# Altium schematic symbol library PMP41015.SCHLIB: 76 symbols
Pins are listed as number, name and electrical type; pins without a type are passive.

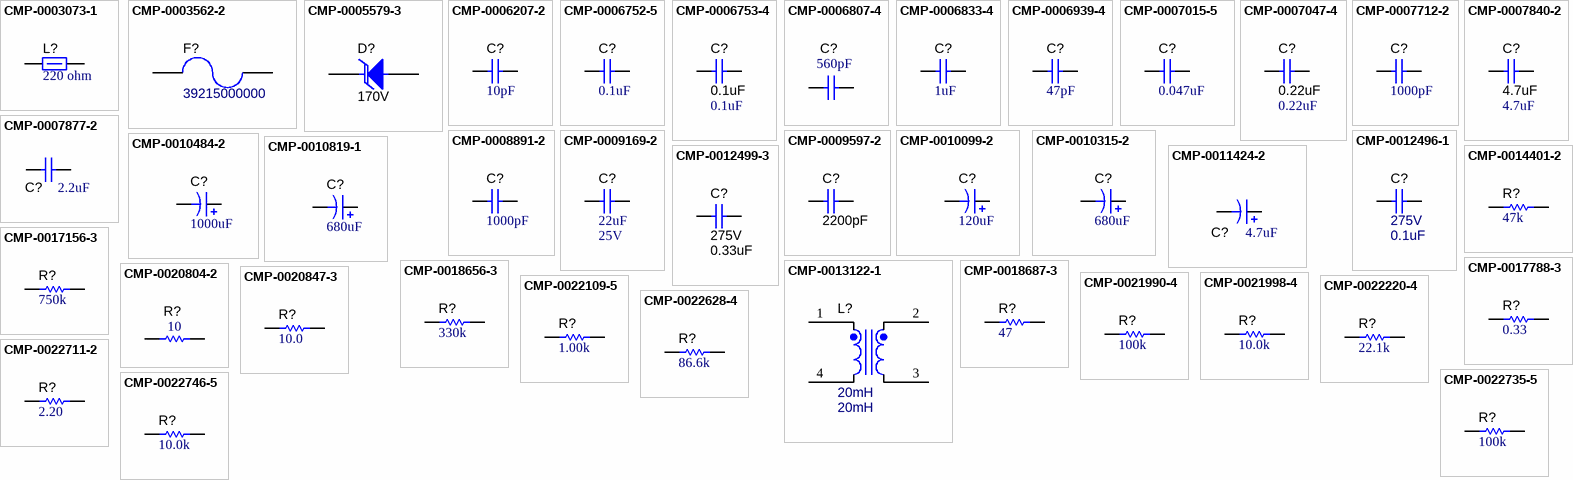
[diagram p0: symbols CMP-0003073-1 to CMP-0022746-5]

## CMP-0003073-1
designator L?  ValueDisplayed: 220 ohm  (hidden comment: CMP-0003073-1)
Ferrite Bead, 220 ohm @ 100 MHz, 2 A, 0805; PartNumber: 742792022; Manufacturer: Wurth Elektronik; Value: 220 ohm; Imax_A: 2A; DCR_ohm: 50m; Value1: 0.05 ohm; SizeAreaWB_mm2: 6.75; SizeArea_mm2: 2.5; SizeX_mm: 2; SizeY_mm: 1.25; SizeZ_mm: 1.45; ZTyp@100MHz_Ohm: 220; Ztyp@1GHz_Ohm: 190.289
footprint 0805_HV (0805 with 30mil clearance between pads)
footprint 0805M (0805 from SM-752 data)
footprint 0805 (0805 from SM-752 data)
footprint 0805L (0805 from SM-752 data)
footprint 0805_HV1 (Custom footprint based on analyzing multiple manufacturer recommendations)
pins: 1, 2

## CMP-0003562-2
designator F?, comment 39215000000
Fuse, 5 A, 250VAC/VDC, TH; Manufacturer: Littelfuse; Irating_A: 5A; VAC_V: 250V
footprint FUSE_392 (LITTELFUSE)
pins: 1, 2

## CMP-0005579-3
designator D?  value 170V  (hidden comment: CMP-0005579-3)
Diode, TVS, Uni, 170 V, 275 Vc, SMB; PartNumber: SMBJ170A-13-F; Manufacturer: Diodes Inc.; Value1: 600W; SizeAreaWB_mm2: 44.156; SizeArea_mm2: 21.336; SizeX_mm: 5.6; SizeY_mm: 3.81; SizeZ_mm: 2.6; AEC Category: Q101; Vbr_Min: 189V; Vc: 275V; Ipp: 2.2A; Vbr_Max: 217.5V
footprint SMB (Molded Diode, 2-Leads, Body 5.4x3.6mm, IPC Medium Density, based on OnSemi component dimensions)
pins: 1 K, 2 A

## CMP-0006207-2
designator C?  ValueDisplayed: 10pF  (hidden comment: CMP-0006207-2)
CAP, CERM, 10 pF, 50 V, +/- 5%, C0G/NP0, 0402; PartNumber: 500R07S100JV4T; Manufacturer: Johanson Technology; Polarized: N; CompType: Capacitor; Value: 10pF; U/M: EA; Value1: Unknown; VDC_V: 50V; TaMin_C: -55°C; TaMax_C: 125°C; Cap_Case: 0402; SizeArea_mm2: 0.5; SizeAreaWB_mm2: 3; SizeX_mm: 1; SizeZ_mm: 0.6; AEC Category: Q200
footprint 0402 (0402 from SM-752 data)
footprint 0402S (Based on C0402S footprint from PADS legacy)
footprint 0402L (0402 from SM-752 data)
footprint 0402M (0402 from SM-752 data)
pins: 1, 2

## CMP-0006752-5
designator C?  ValueDisplayed: 0.1uF  (hidden comment: CMP-0006752-5)
CAP, CERM, 0.1 uF, 25 V, +/- 5%, X7R, 0603; PartNumber: 06033C104JAT2A; Manufacturer: AVX; Polarized: N; CompType: Capacitor; Value: 0.1uF; U/M: EA; Cap_F: 100nF; ESR_ohm: 50m; Value1: 0.05 ohm; VDC_V: 25V; TaMin_C: -55°C; TaMax_C: 125°C; Cap_Case: 0603; SizeArea_mm2: 1.28; SizeAreaWB_mm2: 4.68; SizeX_mm: 1.6; SizeY_mm: 0.8; SizeZ_mm: 1; AEC Category: Q200
footprint 0603 (0603 from SM-752 data)
footprint 0603_HV (Ernesto recommended land pattern.  26 mil between pads.)
footprint 0603L (0603 from SM-752 data)
footprint 0603S
footprint 0603M (0603 from SM-752 data)
pins: 1, 2

## CMP-0006753-4
designator C?, comment 0.1uF
CAP, CERM, 0.1 uF, 25 V, +/- 10%, X7R, 0603; PartNumber: 06033C104KAT2A; Manufacturer: AVX; Polarized: N; CompType: Capacitor; U/M: EA; Cap_F: 100nF; ESR_ohm: 50m; Value1: 0.05 ohm; VDC_V: 25V; TaMin_C: -55°C; TaMax_C: 125°C; Cap_Case: 0603; SizeArea_mm2: 1.28; SizeAreaWB_mm2: 4.68; SizeX_mm: 1.6; SizeY_mm: 0.8; SizeZ_mm: 1; AEC Category: Q200
footprint 0603 (0603 from SM-752 data)
footprint 0603_HV (Ernesto recommended land pattern.  26 mil between pads.)
footprint 0603L (0603 from SM-752 data)
footprint 0603S
footprint 0603M (0603 from SM-752 data)
pins: 1, 2

## CMP-0006807-4
designator C?, comment ValueDisplayed: 560pF  (hidden comment: 06035C561KAT2A)
CAP, CERM, 560 pF, 50 V, +/- 10%, X7R, 0603; Manufacturer: AVX; Polarized: N; CompType: Capacitor; Value: 560pF; U/M: EA; Value1: Unknown; VDC_V: 50V; TaMin_C: -55°C; TaMax_C: 125°C; Cap_Case: 0603; SizeArea_mm2: 1.28; SizeAreaWB_mm2: 4.68; SizeX_mm: 1.6; SizeY_mm: 0.8; SizeZ_mm: 1; AEC Category: Q200
footprint 0603 (0603 from SM-752 data)
footprint 0603_HV (Ernesto recommended land pattern.  26 mil between pads.)
footprint 0603L (0603 from SM-752 data)
footprint 0603S
footprint 0603M (0603 from SM-752 data)
pins: 1, 2

## CMP-0006833-4
designator C?  ValueDisplayed: 1uF  (hidden comment: CMP-0006833-4)
CAP, CERM, 1 uF, 25 V, +/- 10%, X7R, 0603; PartNumber: 885012206076; Manufacturer: Wurth Elektronik; Polarized: N; CompType: Capacitor; Value: 1uF; U/M: EA; Cap_F: 1µF; Value1: Unknown; VDC_V: 25V; TaMin_C: -55°C; TaMax_C: 125°C; Cap_Case: 0603; SizeArea_mm2: 1.28; SizeAreaWB_mm2: 4.68; SizeX_mm: 1.6; SizeY_mm: 0.8; SizeZ_mm: 1; AEC Category: Q200
footprint 0603 (0603 from SM-752 data)
footprint 0603_HV (Ernesto recommended land pattern.  26 mil between pads.)
footprint 0603L (0603 from SM-752 data)
footprint 0603S
footprint 0603M (0603 from SM-752 data)
pins: 1, 2

## CMP-0006939-4
designator C?  ValueDisplayed: 47pF  (hidden comment: CMP-0006939-4)
CAP, CERM, 47 pF, 50 V, +/- 5%, C0G/NP0, 0603; PartNumber: C0603C470J5GACTU; Manufacturer: Kemet; Manufacturer Part Number: C0603C221J5GACTU; Polarized: N; CompType: Capacitor; Value: 47pF; U/M: EA; Value1: Unknown; VDC_V: 50V; TaMin_C: -55°C; TaMax_C: 125°C; Cap_Case: 0603; SizeArea_mm2: 1.28; SizeAreaWB_mm2: 4.68; SizeX_mm: 1.6; SizeY_mm: 0.8; SizeZ_mm: 1; AEC Category: Q200
footprint 0603 (0603 from SM-752 data)
footprint 0603_HV (Ernesto recommended land pattern.  26 mil between pads.)
footprint 0603L (0603 from SM-752 data)
footprint 0603S
footprint 0603M (0603 from SM-752 data)
pins: 1, 2

## CMP-0007015-5
designator C?  ValueDisplayed: 0.047uF  (hidden comment: CMP-0007015-5)
CAP, CERM, 0.047 uF, 50 V, +/- 10%, X5R, 0603; PartNumber: C1608X5R1H473K080AA; Manufacturer: TDK; Polarized: N; CompType: Capacitor; U/M: EA; Cap_F: 47nF; ESR_ohm: 49.007m; Value1: 0.049007 ohm; VDC_V: 50V; IRMS_A: 767.528mA; TaMin_C: -55°C; TaMax_C: 85°C; Cap_Case: 0603; SizeArea_mm2: 1.28; SizeAreaWB_mm2: 4.68; SizeX_mm: 1.6; SizeY_mm: 0.8; SizeZ_mm: 1; AEC Category: Q200
footprint 0603 (0603 from SM-752 data)
footprint 0603_HV (Ernesto recommended land pattern.  26 mil between pads.)
footprint 0603L (0603 from SM-752 data)
footprint 0603S
footprint 0603M (0603 from SM-752 data)
pins: 1, 2

## CMP-0007047-4
designator C?, comment 0.22uF
CAP, CERM, 0.22 uF, 50 V, +/- 10%, X7R, 0603; PartNumber: C1608X7R1H224K080AB; Manufacturer: TDK; Polarized: N; CompType: Capacitor; U/M: EA; Cap_F: 220nF; ESR_ohm: 21.699m; Value1: 0.021699 ohm; VDC_V: 50V; IRMS_A: 1.125A; TaMin_C: -55°C; TaMax_C: 125°C; Cap_Case: 0603; SizeArea_mm2: 1.28; SizeAreaWB_mm2: 4.68; SizeX_mm: 1.6; SizeY_mm: 0.8; SizeZ_mm: 1; AEC Category: Q200
footprint 0603 (0603 from SM-752 data)
footprint 0603_HV (Ernesto recommended land pattern.  26 mil between pads.)
footprint 0603L (0603 from SM-752 data)
footprint 0603S
footprint 0603M (0603 from SM-752 data)
pins: 1, 2

## CMP-0007712-2
designator C?  ValueDisplayed: 1000pF  (hidden comment: CMP-0007712-2)
CAP, CERM, 1000 pF, 630 V, +/- 5%, X7R, 0805; PartNumber: C0805C102JBRACTU; Manufacturer: Kemet; Polarized: N; CompType: Capacitor; Value: 1000pF; U/M: EA; Cap_F: 1nF; Value1: Unknown; VDC_V: 630V; TaMin_C: -55°C; TaMax_C: 125°C; Cap_Case: 0805; SizeArea_mm2: 2.5; SizeAreaWB_mm2: 6.75; SizeX_mm: 2; SizeY_mm: 1.25; SizeZ_mm: 1.45; AEC Category: Q200
footprint 0805_HV (0805 with 30mil clearance between pads)
footprint 0805M (0805 from SM-752 data)
footprint 0805 (0805 from SM-752 data)
footprint 0805L (0805 from SM-752 data)
footprint 0805_HV1 (Custom footprint based on analyzing multiple manufacturer recommendations)
pins: 1, 2

## CMP-0007840-2
designator C?, comment 4.7uF
CAP, CERM, 4.7 uF, 50 V, +/- 10%, X5R, 0805; PartNumber: C2012X5R1H475K125AB; Manufacturer: TDK; Polarized: N; CompType: Capacitor; U/M: EA; Cap_F: 4.7µF; ESR_ohm: 2.346m; Value1: 0.002346 ohm; VDC_V: 50V; IRMS_A: 4.2602A; TaMin_C: -55°C; TaMax_C: 85°C; Cap_Case: 0805; SizeArea_mm2: 2.5; SizeAreaWB_mm2: 6.75; SizeX_mm: 2; SizeY_mm: 1.25; SizeZ_mm: 1.45; AEC Category: Q200
footprint 0805_HV (0805 with 30mil clearance between pads)
footprint 0805M (0805 from SM-752 data)
footprint 0805 (0805 from SM-752 data)
footprint 0805L (0805 from SM-752 data)
footprint 0805_HV1 (Custom footprint based on analyzing multiple manufacturer recommendations)
pins: 1, 2

## CMP-0007877-2
designator C?, comment ValueDisplayed: 2.2uF  (hidden comment: C2012X7R1H225K125AC)
CAP, CERM, 2.2 uF, 50 V, +/- 10%, X7R, 0805; Manufacturer: TDK; Polarized: N; CompType: Capacitor; Value: 2.2uF; U/M: EA; Cap_F: 2.2µF; ESR_ohm: 3.66m; Value1: 0.00366 ohm; VDC_V: 50V; IRMS_A: 3.4121A; TaMin_C: -55°C; TaMax_C: 125°C; Cap_Case: 0805; SizeArea_mm2: 2.5; SizeAreaWB_mm2: 6.75; SizeX_mm: 2; SizeY_mm: 1.25; SizeZ_mm: 1.45; AEC Category: Q200
footprint 0805_HV (0805 with 30mil clearance between pads)
footprint 0805M (0805 from SM-752 data)
footprint 0805 (0805 from SM-752 data)
footprint 0805L (0805 from SM-752 data)
footprint 0805_HV1 (Custom footprint based on analyzing multiple manufacturer recommendations)
pins: 1, 2

## CMP-0008891-2
designator C?  ValueDisplayed: 1000pF  (hidden comment: CMP-0008891-2)
CAP, CERM, 1000 pF, 630 V, +/- 5%, U2J, 1206; PartNumber: GRM31A7U2J102JW31D; Manufacturer: MuRata; Polarized: N; CompType: Capacitor; Value: 1000pF; U/M: EA; Cap_F: 1nF; Value1: Unknown; VDC_V: 630V; TaMin_C: -55°C; TaMax_C: 125°C; Cap_Case: 1206; SizeArea_mm2: 5.12; SizeAreaWB_mm2: 10.92; SizeX_mm: 3.2; SizeY_mm: 1.6; SizeZ_mm: 1.35; AEC Category: Q200
footprint 1206 (1206 from SM-752 data)
footprint 1206L (1206 from SM-752 data)
footprint 1206M (1206 from SM-752 data)
pins: 1, 2

## CMP-0009169-2
designator C?  ValueDisplayed: 22uF  VDC_V: 25V
CAP, CERM, 22 uF, 25 V, +/- 10%, X5R, 1210; PartNumber: CL32A226KAJNNNE; Manufacturer: Samsung Electro-Mechanics; Polarized: N; CompType: Capacitor; Value: 22uF; U/M: EA; Cap_F: 22µF; Value1: Unknown; TaMin_C: -55°C; TaMax_C: 85°C; Cap_Case: 1210; SizeArea_mm2: 8; SizeAreaWB_mm2: 14.7; SizeX_mm: 3.2; SizeY_mm: 2.5; SizeZ_mm: 1.35; AEC Category: Q200
footprint 1210 (1210 from SM-752 data)
footprint 1210L (1210 from SM-752 data)
footprint 1210M (1210 from SM-752 data)
pins: 1, 2

## CMP-0009597-2
designator C?, comment ValueDisplayed: 2200pF  (hidden comment: CD45-E2GA222M-NKA)
CAP, CERM, 2200 pF,  V, +/- 20%, E, D9xT6mm; Manufacturer: TDK; TaMin_C: -25°C; Polarized: N; SizeAreaWB_mm2: 101.2; Value1: Unknown; U/M: EA; Value: 2200pF; TaMax_C: 125°C; SizeZ_mm: 13; SizeX_mm: 10.65; SizeY_mm: 6; Cap_Case: 9x6x13mm; SizeArea_mm2: 63.9; CompType: Capacitor; Cap_F: 2.2nF; AEC Category: Q200
footprint CD45_900x600x1300 (TH, 2-Leads, Dia 9mm, Pin Spacing 10 mm)
pins: 1, 2

## CMP-0010099-2
designator C?  ValueDisplayed: 120uF  (hidden comment: CMP-0010099-2)
CAP, AL, 120 uF, 450 V, +/- 20%, TH; PartNumber: LLS2W121MELA; Manufacturer: Nichicon; Polarized: Y; CompType: Capacitor; Value: 120uF; U/M: EA; Cap_F: 120µF; Value1: Unknown; VDC_V: 450V; IRMS_A: 1.09A; TaMin_C: -25°C; TaMax_C: 85°C; Cap_Case: 25x30mm; SizeAreaWB_mm2: 729; SizeArea_mm2: 625; SizeX_mm: 25; SizeZ_mm: 32; AEC Category: Q200; AEC Qualified: N
footprint Nichicon_2500x3000_Snap
pins: 1 +, 2 -

## CMP-0010315-2
designator C?  ValueDisplayed: 680uF  (hidden comment: CMP-0010315-2)
CAP, AL, 680 uF, 35 V, +/- 20%, 0.041 ohm, AEC-Q200 Grade 1, TH; PartNumber: B41896C7687M000; Manufacturer: TDK; Polarized: Y; CompType: Capacitor; Value: 680uF; U/M: EA; Cap_F: 680µF; VDC_V: 35V; ESR_ohm: 41m; IRMS_A: 2.28A; TaMin_C: -55°C; TaMax_C: 125°C; Cap_Case: 12.5x25mm; SizeAreaWB_mm2: 210.25; SizeArea_mm2: 156.25; SizeX_mm: 12.5; SizeZ_mm: 27; AEC Category: Q200; AEC Grade: 1
footprint B41896_1250x2500 (TH, 2-Leads, Dia 12.5mm, Pin Spacing 5mm)
pins: 1 +, 2 -

## CMP-0010484-2
designator C?, comment ValueDisplayed: 1000uF  (hidden comment: ELXZ350ELL102MK25S)
CAP, AL, 1000 uF, 35 V, +/- 20%, AEC-Q200 Grade 2, TH; Manufacturer: Chemi-Con; Polarized: Y; CompType: Capacitor; Value: 1000uF; U/M: EA; Cap_F: 1mF; Value1: Unknown; VDC_V: 35V; IRMS_A: 1.95A; TaMin_C: -55°C; TaMax_C: 105°C; Cap_Case: 12.5x25mm; SizeAreaWB_mm2: 210.25; SizeArea_mm2: 156.25; SizeX_mm: 12.5; SizeZ_mm: 21.5; AEC Category: Q200; AEC Grade: 2
footprint Chemi-Con_1250x2000 (TH, 2-Leads, Dia 12.5mm, Lead Sapcing 5mm)
pins: 1 +, 2 -

## CMP-0010819-1
designator C?  ValueDisplayed: 680uF  (hidden comment: CMP-0010819-1)
CAP, AL, 680 uF, 6.3 V, +/- 20%, SMD; PartNumber: EMVA6R3ADA681MHA0G; Manufacturer: Chemi-Con; Polarized: Y; CompType: Capacitor; Value: 680uF; U/M: EA; Cap_F: 680µF; Value1: Unknown; VDC_V: 6.3V; IRMS_A: 290mA; TaMin_C: -40°C; TaMax_C: 85°C; Cap_Case: HA0; SizeAreaWB_mm2: 106.09; SizeArea_mm2: 68.89; SizeX_mm: 8.3; SizeZ_mm: 10; AEC Category: Q200
footprint CAPSMT_62_HA0 (8 x 10mm:  Chemi-Con HA0)
pins: 1 +, 2 -

## CMP-0011424-2
designator C?  ValueDisplayed: 4.7uF  (hidden comment: CMP-0011424-2)
CAP, AL, 4.7 uF, 50 V, +/- 20%, 1.52 ohm, SMD; PartNumber: UUD1H4R7MCL1GS; Manufacturer: Nichicon; Polarized: Y; CompType: Capacitor; Value: 4.7uF; U/M: EA; Cap_F: 4.7µF; VDC_V: 50V; ESR_ohm: 1.52; IRMS_A: 85mA; TaMin_C: -55°C; TaMax_C: 105°C; Cap_Case: 5x5.8; SizeAreaWB_mm2: 58.4; SizeArea_mm2: 31.8; SizeX_mm: 6; SizeY_mm: 5.3; AEC Category: Q200
footprint SM_RADIAL_5MM (Nichicon 5x5.8)
pins: 1 +, 2 -

## CMP-0012496-1
designator C?, comment VDC_V: 275V  ValueDisplayed: 0.1uF  (hidden comment: ECQ-U2A104ML)
CAP, Film, 0.1 uF, 275 V, +/- 20%, TH; Manufacturer: Panasonic; TaMin_C: -40°C; Polarized: N; Value1: Unknown; U/M: EA; Value: 0.1uF; TaMax_C: 100°C; Cap_Case: Radial 17.5x5.5x12.5; CompType: Capacitor; Cap_F: 100nF; AEC Category: Q200
footprint CAPRR1500W60L1750T550H1250 (PANASONIC)
pins: 1, 2

## CMP-0012499-3
designator C?, comment VDC_V: 275V  ValueDisplayed: 0.33uF  (hidden comment: ECQ-U2A334ML)
CAP, Film, 0.33 uF, 275 V, +/- 20%, TH; Manufacturer: Panasonic; TaMin_C: -40°C; Polarized: N; SizeAreaWB_mm2: 224.25; Value1: Unknown; Value: 0.33uF; TaMax_C: 100°C; SizeZ_mm: 18; SizeX_mm: 17.5; SizeY_mm: 9.5; Cap_Case: Radial,17.5x17.5x9.5mm; SizeArea_mm2: 166.25; CompType: Capacitor; Cap_F: 330nF; AEC Category: Q200
footprint CAPRR1500W80L1750T950H1750 (PANASONIC)
pins: 1, 2

## CMP-0013122-1
designator L?, comment value 20mH  (hidden comment: 744823220)
Coupled inductor, 20 mH, 1.5 A, 0.27 ohm, TH; Manufacturer: Wurth Elektronik; SizeAreaWB_mm2: 513; DCR_ohm: 0.27; SizeZ_mm: 26.5; SizeX_mm: 25; SizeY_mm: 17; SizeArea_mm2: 425
footprint WE-CMB_M (Wurth)
pins: 1, 2, 3, 4
1 alternate drawing of the same symbol

## CMP-0014401-2
designator R?  ValueDisplayed: 47k  (hidden comment: CMP-0014401-2)
RES, 47 k, 5%, 2 W, AEC-Q200 Grade 0, Axial resistor; PartNumber: PR02000204702JR500; Manufacturer: Vishay-Bccomponents; Manufacturer: Bc Components; Value: 47k; Value_Code: 47k0; Power_W: 2W; VDC_V: 500V; TempCo: 250 ppm/C; EIA_Code: E24; U/M: EA; AEC Category: Q200; AEC Qualified: Y; AEC Grade: 0
footprint PR02 (Vishay-BC Components)
pins: 1, 2

## CMP-0017156-3
designator R?  ValueDisplayed: 750k  (hidden comment: CMP-0017156-3)
RES, 750 k, 1%, 0.25 W, AEC-Q200 Grade 0, 1206; PartNumber: CRCW1206750KFKEA; Manufacturer: Vishay-Dale; Manufacturer: Vishay/Dale; CompType: Resistor; Value: 750k; Power_W: 250mW; Value2: 0.25W; VDC_V: 200V; TempCo: 100 ppm/C; SizeArea_mm2: 5.12; SizeX_mm: 3.2; SizeY_mm: 1.6; SizeZ_mm: 1.35; EIA_Code: E96; AEC Category: Q200; AEC Qualified: Y; AEC Grade: 0
footprint 1206 (1206 from SM-752 data)
footprint 1206L (1206 from SM-752 data)
footprint 1206M (1206 from SM-752 data)
pins: 1, 2

## CMP-0017788-3
designator R?  ValueDisplayed: 0.33  (hidden comment: CMP-0017788-3)
RES, 0.33, 1%, 0.25 W, AEC-Q200 Grade 0, 1206; PartNumber: ERJ-8RQFR33V; Manufacturer: Panasonic; CompType: Resistor; Value: 0.33; Value_Code: R330; Power_W: 250mW; Value2: 0.25W; TempCo: 250 ppm/C; SizeArea_mm2: 5.12; SizeX_mm: 3.2; SizeY_mm: 1.6; SizeZ_mm: 1.35; EIA_Code: E96; AEC Category: Q200; AEC Qualified: Y; AEC Grade: 0; SizeAreaWB_mm2: 10.92
footprint 1206 (1206 from SM-752 data)
footprint 1206M (1206 from SM-752 data)
footprint 1206L (1206 from SM-752 data)
pins: 1, 2

## CMP-0018656-3
designator R?  ValueDisplayed: 330k  (hidden comment: CMP-0018656-3)
RES, 330 k, 5%, 0.25 W, AEC-Q200 Grade 0, 1206; PartNumber: CRCW1206330KJNEA; Manufacturer: Vishay-Dale; Manufacturer: Vishay/Dale; CompType: Resistor; Value: 330k; Power_W: 250mW; Value2: 0.25W; VDC_V: 200V; TempCo: 200 ppm/C; SizeArea_mm2: 5.12; SizeX_mm: 3.2; SizeY_mm: 1.6; SizeZ_mm: 1.35; EIA_Code: E24; AEC Category: Q200; AEC Qualified: Y; AEC Grade: 0
footprint 1206 (1206 from SM-752 data)
footprint 1206L (1206 from SM-752 data)
footprint 1206M (1206 from SM-752 data)
pins: 1, 2

## CMP-0018687-3
designator R?  ValueDisplayed: 47  (hidden comment: CMP-0018687-3)
RES, 47, 5%, 0.25 W, AEC-Q200 Grade 0, 1206; PartNumber: CRCW120647R0JNEA; Manufacturer: Vishay-Dale; Manufacturer: Vishay/Dale; CompType: Resistor; Value: 47; Value_Code: 47R0; Power_W: 250mW; Value2: 0.25W; VDC_V: 200V; TempCo: 200 ppm/C; SizeArea_mm2: 5.12; SizeX_mm: 3.2; SizeY_mm: 1.6; SizeZ_mm: 1.35; EIA_Code: E24; AEC Category: Q200; AEC Qualified: Y; AEC Grade: 0
footprint 1206 (1206 from SM-752 data)
footprint 1206L (1206 from SM-752 data)
footprint 1206M (1206 from SM-752 data)
pins: 1, 2

## CMP-0020804-2
designator R?  ValueDisplayed: 10  (hidden comment: CMP-0020804-2)
RES, 10, 5%, 0.125 W, 0805; PartNumber: RC0805JR-0710RL; Manufacturer: Yageo America; CompType: Resistor; Value: 10; Value_Code: 10R0; Power_W: 125mW; Value2: 0.125W; VDC_V: 150V; TempCo: 200 ppm/C; SizeArea_mm2: 2.5; SizeX_mm: 2; SizeY_mm: 1.25; SizeZ_mm: 1.45; EIA_Code: E24; U/M: EA; AEC Category: Q200
footprint 0805_HV (0805 with 30mil clearance between pads)
footprint 0805M (0805 from SM-752 data)
footprint 0805 (0805 from SM-752 data)
footprint 0805L (0805 from SM-752 data)
footprint 0805_HV1 (Custom footprint based on analyzing multiple manufacturer recommendations)
pins: 1, 2

## CMP-0020847-3
designator R?  ValueDisplayed: 10.0  (hidden comment: CMP-0020847-3)
RES, 10.0, 1%, 0.125 W, AEC-Q200 Grade 0, 0805; PartNumber: CRCW080510R0FKEA; Manufacturer: Vishay-Dale; Manufacturer: Vishay; CompType: Resistor; Value: 10.0; Res_ohm: 10; Value_Code: 10R0; Power_W: 125mW; Value2: 0.125W; VDC_V: 150V; TempCo: 100 ppm/C; SizeArea_mm2: 2.5; SizeX_mm: 2; SizeY_mm: 1.25; SizeZ_mm: 1.45; EIA_Code: E96; AEC Category: Q200; AEC Qualified: Y; AEC Grade: 0
footprint 0805_HV (0805 with 30mil clearance between pads)
footprint 0805M (0805 from SM-752 data)
footprint 0805 (0805 from SM-752 data)
footprint 0805L (0805 from SM-752 data)
footprint 0805_HV1 (Custom footprint based on analyzing multiple manufacturer recommendations)
pins: 1, 2

## CMP-0021990-4
designator R?  ValueDisplayed: 100k  (hidden comment: CMP-0021990-4)
RES, 100 k, 1%, 0.1 W, AEC-Q200 Grade 0, 0603; PartNumber: CRCW0603100KFKEA; Manufacturer: Vishay-Dale; Manufacturer: Vishay/Dale; CompType: Resistor; Value: 100k; Power_W: 100mW; Value2: 0.1W; VDC_V: 75V; TempCo: 100 ppm/C; SizeArea_mm2: 1.28; SizeX_mm: 1.6; SizeY_mm: 0.8; SizeZ_mm: 1; EIA_Code: E96; AEC Category: Q200; AEC Qualified: Y; AEC Grade: 0
footprint 0603 (0603 from SM-752 data)
footprint 0603_HV (Ernesto recommended land pattern.  26 mil between pads.)
footprint 0603L (0603 from SM-752 data)
footprint 0603S
footprint 0603M (0603 from SM-752 data)
pins: 1, 2

## CMP-0021998-4
designator R?  ValueDisplayed: 10.0k  (hidden comment: CMP-0021998-4)
RES, 10.0 k, 1%, 0.1 W, AEC-Q200 Grade 0, 0603; PartNumber: CRCW060310K0FKEA; Manufacturer: Vishay-Dale; Manufacturer: Vishay / Dale; CompType: Resistor; Value: 10.0k; Res_ohm: 10k; Value_Code: 10k0; Power_W: 100mW; Value2: 0.1W; VDC_V: 75V; TempCo: 100 ppm/C; SizeArea_mm2: 1.28; SizeX_mm: 1.6; SizeY_mm: 0.8; SizeZ_mm: 1; EIA_Code: E96; AEC Category: Q200; AEC Qualified: Y; AEC Grade: 0
footprint 0603 (0603 from SM-752 data)
footprint 0603_HV (Ernesto recommended land pattern.  26 mil between pads.)
footprint 0603L (0603 from SM-752 data)
footprint 0603S
footprint 0603M (0603 from SM-752 data)
pins: 1, 2

## CMP-0022109-5
designator R?  ValueDisplayed: 1.00k  (hidden comment: CMP-0022109-5)
RES, 1.00 k, 1%, 0.1 W, AEC-Q200 Grade 0, 0603; PartNumber: CRCW06031K00FKEA; Manufacturer: Vishay-Dale; Manufacturer: Vishay / Dale; CompType: Resistor; Value: 1.00k; Res_ohm: 1k; Value_Code: 1k00; Power_W: 100mW; Value2: 0.1W; VDC_V: 75V; TempCo: 100 ppm/C; SizeArea_mm2: 1.28; SizeX_mm: 1.6; SizeY_mm: 0.8; SizeZ_mm: 1; EIA_Code: E96; AEC Category: Q200; AEC Qualified: Y; AEC Grade: 0
footprint 0603 (0603 from SM-752 data)
footprint 0603_HV (Ernesto recommended land pattern.  26 mil between pads.)
footprint 0603L (0603 from SM-752 data)
footprint 0603S
footprint 0603M (0603 from SM-752 data)
pins: 1, 2

## CMP-0022220-4
designator R?  ValueDisplayed: 22.1k  (hidden comment: CMP-0022220-4)
RES, 22.1 k, 1%, 0.1 W, AEC-Q200 Grade 0, 0603; PartNumber: CRCW060322K1FKEA; Manufacturer: Vishay-Dale; Manufacturer: Vishay/Dale; CompType: Resistor; Value: 22.1k; Value_Code: 22k1; Power_W: 100mW; Value2: 0.1W; VDC_V: 75V; TempCo: 100 ppm/C; SizeArea_mm2: 1.28; SizeX_mm: 1.6; SizeY_mm: 0.8; SizeZ_mm: 1; EIA_Code: E96; AEC Category: Q200; AEC Qualified: Y; AEC Grade: 0
footprint 0603 (0603 from SM-752 data)
footprint 0603_HV (Ernesto recommended land pattern.  26 mil between pads.)
footprint 0603L (0603 from SM-752 data)
footprint 0603S
footprint 0603M (0603 from SM-752 data)
pins: 1, 2

## CMP-0022628-4
designator R?  ValueDisplayed: 86.6k  (hidden comment: CMP-0022628-4)
RES, 86.6 k, 1%, 0.1 W, AEC-Q200 Grade 0, 0603; PartNumber: CRCW060386K6FKEA; Manufacturer: Vishay-Dale; Manufacturer: Vishay/Dale; CompType: Resistor; Value: 86.6k; Value_Code: 86k6; Power_W: 100mW; Value2: 0.1W; VDC_V: 75V; TempCo: 100 ppm/C; SizeArea_mm2: 1.28; SizeX_mm: 1.6; SizeY_mm: 0.8; SizeZ_mm: 1; EIA_Code: E96; AEC Category: Q200; AEC Qualified: Y; AEC Grade: 0
footprint 0603 (0603 from SM-752 data)
footprint 0603_HV (Ernesto recommended land pattern.  26 mil between pads.)
footprint 0603L (0603 from SM-752 data)
footprint 0603S
footprint 0603M (0603 from SM-752 data)
pins: 1, 2

## CMP-0022711-2
designator R?, comment ValueDisplayed: 2.20  (hidden comment: ERJ-3RQF2R2V)
RES, 2.20, 1%, 0.1 W, 0603; Manufacturer: Panasonic; CompType: Resistor; Value: 2.20; Res_ohm: 2.2; Value_Code: 2R20; Power_W: 100mW; Value2: 0.1W; TempCo: 200 ppm/C; SizeArea_mm2: 1.28; SizeX_mm: 1.6; SizeY_mm: 0.8; SizeZ_mm: 1; U/M: EA; AEC Category: Q200
footprint 0603 (0603 from SM-752 data)
footprint 0603_HV (Ernesto recommended land pattern.  26 mil between pads.)
footprint 0603L (0603 from SM-752 data)
footprint 0603S
footprint 0603M (0603 from SM-752 data)
pins: 1, 2

## CMP-0022735-5
designator R?  ValueDisplayed: 100k  (hidden comment: CMP-0022735-5)
RES, 100 k, 1%, 0.1 W, 0603; PartNumber: RC0603FR-07100KL; Manufacturer: Yageo; CompType: Resistor; Value: 100k; Power_W: 100mW; Value2: 0.1W; VDC_V: 75V; TempCo: 100 ppm/C; SizeArea_mm2: 1.28; SizeX_mm: 1.6; SizeY_mm: 0.8; SizeZ_mm: 1; EIA_Code: E96; AEC Category: Q200; AEC Qualified: N; SizeAreaWB_mm2: 4.68
footprint 0603 (0603 from SM-752 data)
footprint 0603_HV (Ernesto recommended land pattern.  26 mil between pads.)
footprint 0603L (0603 from SM-752 data)
footprint 0603S
footprint 0603M (0603 from SM-752 data)
pins: 1, 2

## CMP-0022746-5
designator R?  ValueDisplayed: 10.0k  (hidden comment: CMP-0022746-5)
RES, 10.0 k, 1%, 0.1 W, 0603; PartNumber: RC0603FR-0710KL; Manufacturer: Yageo; CompType: Resistor; Value: 10.0k; Res_ohm: 10k; Value_Code: 10k0; Power_W: 100mW; Value2: 0.1W; VDC_V: 75V; TempCo: 100 ppm/C; SizeArea_mm2: 1.28; SizeX_mm: 1.6; SizeY_mm: 0.8; SizeZ_mm: 1; EIA_Code: E96; AEC Category: Q200; AEC Qualified: N; SizeAreaWB_mm2: 4.68
footprint 0603 (0603 from SM-752 data)
footprint 0603_HV (Ernesto recommended land pattern.  26 mil between pads.)
footprint 0603L (0603 from SM-752 data)
footprint 0603S
footprint 0603M (0603 from SM-752 data)
pins: 1, 2

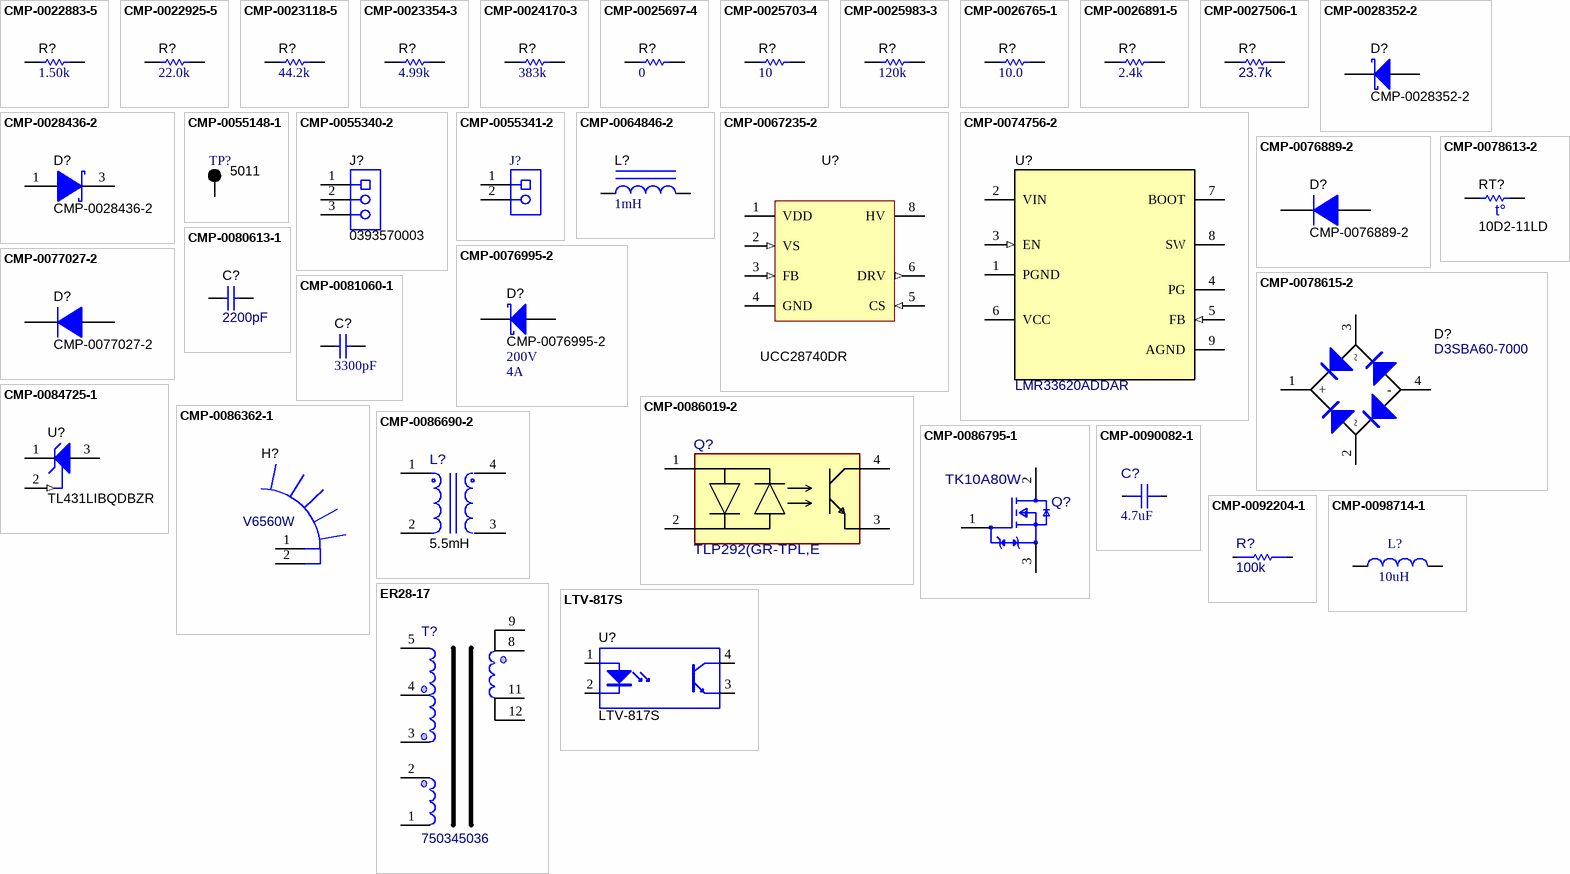
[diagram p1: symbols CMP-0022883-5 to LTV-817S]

## CMP-0022883-5
designator R?  ValueDisplayed: 1.50k  (hidden comment: CMP-0022883-5)
RES, 1.50 k, 1%, 0.1 W, 0603; PartNumber: RC0603FR-071K5L; Manufacturer: Yageo; CompType: Resistor; Value: 1.50k; Res_ohm: 1.5k; Value_Code: 1k50; Power_W: 100mW; Value2: 0.1W; VDC_V: 75V; TempCo: 100 ppm/C; SizeArea_mm2: 1.28; SizeX_mm: 1.6; SizeY_mm: 0.8; SizeZ_mm: 1; EIA_Code: E96; AEC Category: Q200; AEC Qualified: N; SizeAreaWB_mm2: 4.68
footprint 0603 (0603 from SM-752 data)
footprint 0603_HV (Ernesto recommended land pattern.  26 mil between pads.)
footprint 0603L (0603 from SM-752 data)
footprint 0603S
footprint 0603M (0603 from SM-752 data)
pins: 1, 2

## CMP-0022925-5
designator R?  ValueDisplayed: 22.0k  (hidden comment: CMP-0022925-5)
RES, 22.0 k, 1%, 0.1 W, 0603; PartNumber: RC0603FR-0722KL; Manufacturer: Yageo; CompType: Resistor; Value: 22.0k; Res_ohm: 22k; Value_Code: 22k0; Power_W: 100mW; Value2: 0.1W; VDC_V: 75V; TempCo: 100 ppm/C; SizeArea_mm2: 1.28; SizeX_mm: 1.6; SizeY_mm: 0.8; SizeZ_mm: 1; AEC Category: Q200; AEC Qualified: N; SizeAreaWB_mm2: 4.68
footprint 0603 (0603 from SM-752 data)
footprint 0603_HV (Ernesto recommended land pattern.  26 mil between pads.)
footprint 0603L (0603 from SM-752 data)
footprint 0603S
footprint 0603M (0603 from SM-752 data)
pins: 1, 2

## CMP-0023118-5
designator R?  ValueDisplayed: 44.2k  (hidden comment: CMP-0023118-5)
RES, 44.2 k, 1%, 0.1 W, 0603; PartNumber: RC0603FR-0744K2L; Manufacturer: Yageo; CompType: Resistor; Value: 44.2k; Value_Code: 44k2; Power_W: 100mW; Value2: 0.1W; VDC_V: 75V; TempCo: 100 ppm/C; SizeArea_mm2: 1.28; SizeX_mm: 1.6; SizeY_mm: 0.8; SizeZ_mm: 1; EIA_Code: E96; AEC Category: Q200; AEC Qualified: N; SizeAreaWB_mm2: 4.68
footprint 0603 (0603 from SM-752 data)
footprint 0603_HV (Ernesto recommended land pattern.  26 mil between pads.)
footprint 0603L (0603 from SM-752 data)
footprint 0603S
footprint 0603M (0603 from SM-752 data)
pins: 1, 2

## CMP-0023354-3
designator R?  ValueDisplayed: 4.99k  (hidden comment: CMP-0023354-3)
RES, 4.99 k, 0.1%, 0.063 W, 0603; PartNumber: CPF0603B4K99E; Manufacturer: TE Connectivity; CompType: Resistor; Value: 4.99k; Value_Code: 4k99; Power_W: 63mW; Value2: 0.063W; VDC_V: 50V; TempCo: 25 ppm/C; SizeArea_mm2: 1.28; SizeX_mm: 1.6; SizeY_mm: 0.8; SizeZ_mm: 1; EIA_Code: E192; U/M: EA; AEC Category: Q200
footprint 0603 (0603 from SM-752 data)
footprint 0603_HV (Ernesto recommended land pattern.  26 mil between pads.)
footprint 0603L (0603 from SM-752 data)
footprint 0603S
footprint 0603M (0603 from SM-752 data)
pins: 1, 2

## CMP-0024170-3
designator R?  ValueDisplayed: 383k  (hidden comment: CMP-0024170-3)
RES, 383 k, 0.1%, 0.1 W, 0603; PartNumber: RT0603BRD07383KL; Manufacturer: Yageo America; CompType: Resistor; Value: 383k; Power_W: 100mW; Value2: 0.1W; VDC_V: 75V; TempCo: 25 ppm/C; SizeArea_mm2: 1.28; SizeX_mm: 1.6; SizeY_mm: 0.8; SizeZ_mm: 1; EIA_Code: E192; U/M: EA; AEC Category: Q200
footprint 0603 (0603 from SM-752 data)
footprint 0603_HV (Ernesto recommended land pattern.  26 mil between pads.)
footprint 0603L (0603 from SM-752 data)
footprint 0603S
footprint 0603M (0603 from SM-752 data)
pins: 1, 2

## CMP-0025697-4
designator R?  ValueDisplayed: 0  (hidden comment: CMP-0025697-4)
RES, 0, 5%, 0.1 W, AEC-Q200 Grade 0, 0603; PartNumber: CRCW06030000Z0EA; Manufacturer: Vishay-Dale; CompType: Resistor; Value: 0; Value_Code: 0000; Power_W: 100mW; Value2: 0.1W; VDC_V: 75V; TempCo: 200 ppm/C; SizeArea_mm2: 1.28; SizeX_mm: 1.6; SizeY_mm: 0.8; SizeZ_mm: 1; EIA_Code: E24; AEC Category: Q200; AEC Qualified: Y
footprint 0603 (0603 from SM-752 data)
footprint 0603_HV (Ernesto recommended land pattern.  26 mil between pads.)
footprint 0603L (0603 from SM-752 data)
footprint 0603S
footprint 0603M (0603 from SM-752 data)
pins: 1, 2

## CMP-0025703-4
designator R?  ValueDisplayed: 10  (hidden comment: CMP-0025703-4)
RES, 10, 5%, 0.1 W, AEC-Q200 Grade 0, 0603; PartNumber: CRCW060310R0JNEA; Manufacturer: Vishay-Dale; CompType: Resistor; Value: 10; Value_Code: 10R0; Power_W: 100mW; Value2: 0.1W; VDC_V: 75V; TempCo: 200 ppm/C; SizeArea_mm2: 1.28; SizeX_mm: 1.6; SizeY_mm: 0.8; SizeZ_mm: 1; EIA_Code: E24; AEC Category: Q200; AEC Qualified: Y; AEC Grade: 0
footprint 0603 (0603 from SM-752 data)
footprint 0603_HV (Ernesto recommended land pattern.  26 mil between pads.)
footprint 0603L (0603 from SM-752 data)
footprint 0603S
footprint 0603M (0603 from SM-752 data)
pins: 1, 2

## CMP-0025983-3
designator R?  ValueDisplayed: 120k  (hidden comment: CMP-0025983-3)
RES, 120 k, 1%, 0.063 W, AEC-Q200 Grade 0, 0402; PartNumber: CRCW0402120KFKED; Manufacturer: Vishay-Dale; Manufacturer: Vishay / Dale; CompType: Resistor; Value: 120k; Power_W: 63mW; Value2: 0.063W; VDC_V: 50V; TempCo: 100 ppm/C; SizeArea_mm2: 0.5; SizeX_mm: 1; SizeZ_mm: 0.6; AEC Category: Q200; AEC Qualified: Y; AEC Grade: 0
footprint 0402 (0402 from SM-752 data)
footprint 0402S (Based on C0402S footprint from PADS legacy)
footprint 0402L (0402 from SM-752 data)
footprint 0402M (0402 from SM-752 data)
pins: 1, 2

## CMP-0026765-1
designator R?  ValueDisplayed: 10.0  (hidden comment: CMP-0026765-1)
RES, 10.0, 0.1%, 0.063 W, 0402; PartNumber: CPF0402B10RE1; Manufacturer: TE Connectivity; CompType: Resistor; Value: 10.0; Res_ohm: 10; Value_Code: 10R0; Power_W: 63mW; Value2: 0.063W; TempCo: 25 ppm/C; SizeArea_mm2: 0.5; SizeX_mm: 1; SizeZ_mm: 0.35; EIA_Code: E192; U/M: EA; AEC Category: Q200; AEC Qualified: N
footprint CPF0402 (TE Connectivity)
pins: 1, 2

## CMP-0026891-5
designator R?  ValueDisplayed: 2.4k  (hidden comment: CMP-0026891-5)
RES, 2.4 k, 5%, 0.063 W, AEC-Q200 Grade 0, 0402; PartNumber: CRCW04022K40JNED; Manufacturer: Vishay-Dale; Manufacturer: Vishay / Dale; CompType: Resistor; Value: 2.4k; Value_Code: 2k40; Power_W: 63mW; Value2: 0.063W; VDC_V: 50V; TempCo: 200 ppm/C; SizeArea_mm2: 0.5; SizeX_mm: 1; SizeZ_mm: 0.6; EIA_Code: E24; AEC Category: Q200; AEC Qualified: Y; AEC Grade: 0
footprint 0402 (0402 from SM-752 data)
footprint 0402S (Based on C0402S footprint from PADS legacy)
footprint 0402L (0402 from SM-752 data)
footprint 0402M (0402 from SM-752 data)
pins: 1, 2

## CMP-0027506-1
designator R?, comment ValueDisplayed: 23.7k  (hidden comment: RC0201FR-0723K7L)
RES, 23.7 k, 1%, 0.05 W, 0201; Manufacturer: Yageo America; Power_W: 50mW; TempCo: 200 ppm/C; Value_Code: 23k7; U/M: EA; Value: 23.7k; EIA_Code: E96; SizeX_mm: 0.6; SizeY_mm: 0.3; SizeZ_mm: 0.26; Value2: 0.05W; SizeArea_mm2: 0.18; CompType: Resistor; AEC Qualified: N; VDC_V: 25V; AEC Category: Q200
footprint 0201 (Data from Kemet datasheet CC101_COM dated 7/28/11)
footprint 0201_Silk (Data from Kemet datasheet CC101_COM dated 7/28/11)
footprint 0201L (Data from Kemet datasheet CC101_COM dated 7/28/11)
footprint 0201M (Data from Kemet datasheet CC101_COM dated 7/28/11)
pins: 1, 2

## CMP-0028352-2
designator D?
Diode, Schottky, 40 V, 3 A, SMC; PartNumber: B340-13-F; Manufacturer: Diodes Inc.; Manufacturer: Diodes; Vf_V: 500mV; Value: 40V; Value1: 3A; Value2: 0.5V; TJmax_C: 125°C; RJC_CperW: 20; SizeAreaWB_mm2: 83.2686; SizeArea_mm2: 50.5686; SizeX_mm: 8.13; SizeY_mm: 6.22; SizeZ_mm: 2.6; AEC Category: Q101; Green_Lifecycle: Not Set; Green_REACh: Incomplete
footprint SMC (Molded Diode, 2-Leads, Body 6.9x5.8mm, IPC Medium Density, based on OnSemi component dimensions and land patterns)
pins: 1 K, 2 A

## CMP-0028436-2
designator D?
Diode, Schottky, 40 V, 0.2 A, SOT-23; PartNumber: BAS40-7-F; Manufacturer: Diodes Inc.; Manufacturer: Diodes; Vf_V: 800mV; Value: 40V; Value1: 0.2A; Value2: 0.8V; Io_A: 200mA; SizeAreaWB_mm2: 14; SizeArea_mm2: 7.5; SizeX_mm: 2.5; SizeY_mm: 3; SizeZ_mm: 1.1; AEC Category: Q101; Green_Lifecycle: Not Set; Green_REACh: Incomplete
footprint SOT-23 (SOT23, 3-Leads, Body 2.9x1.3mm, Pitch 0.95mm, Lead Span 2.5mm, IPC Medium Density)
footprint SOT-23L (SOT23, 3-Leads, Body 2.9x1.3mm, Pitch 0.95mm, Lead Span 2.5mm, IPC High Density)
footprint SOT-23M (SOT23, 3-Leads, Body 2.9x1.3mm, Pitch 0.95mm, Lead Span 2.5mm, IPC Low Density)
pins: 1 A, 3 K

## CMP-0055148-1
designator TP?, comment 5011
Test Point, Multipurpose, Black, TH; Manufacturer: Keystone; Manufacturer: Keystone Electronics; CNHeader: FALSE; Green_Lifecycle: Active; Green_REACh: Passed; ContactFinish: Silver; CT: TRUE
footprint Keystone5011 (Keystone Multipurpose loops)
pins: 1

## CMP-0055340-2
designator J?, comment 0393570003
Terminal Block, 3.5 mm, 3x1, Tin, TH; Manufacturer: Molex; Green_Lifecycle: Not Set; Green_REACh: Incomplete; CNHeader: FALSE; CT: TRUE
footprint MOLEX_39357-0003 (Terminal Block, 3.5 mm, 3x1, TH)
pins: 1, 2, 3

## CMP-0055341-2
designator J?, comment 0393570002  (value not drawn)
Terminal Block, 3.5 mm, 2x1, Tin, TH; Manufacturer: Molex; Green_Lifecycle: Not Set; Green_REACh: Incomplete; CNHeader: FALSE; CT: TRUE
footprint MOLEX_39357-0002 (Terminal Block, 3.5 mm, 2x1, TH)
pins: 1, 2

## CMP-0064846-2
designator L?  ValueDisplayed: 1mH  (hidden comment: CMP-0064846-2)
Inductor, Shielded Drum Core, Metal Composite, 1 mH, 0.5 A, 1.7 ohm, TH; PartNumber: 768772102; Manufacturer: Wurth Elektronik; Value: 1mH; Imax_A: 500mA; Irms: 0.5A @ 40C rise; Isat: 0.55A @ 10% inductance drop; DCR_ohm: 1.7; Value1: 1.7 ohm; Value2: 0.5A; SizeAreaWB_mm2: 96.04; SizeArea_mm2: 60.84; SizeX_mm: 7.8; SizeZ_mm: 10; AEC Category: Q200; Green_Lifecycle: Active; Green_REACh: Passed
footprint WE-TI_8095 (Wurth WE-TI 8095)
pins: 1, 2

## CMP-0067235-2
designator U?, comment UCC28740DR
Constant-Voltage, Constant-Current Flyback Controller Using Opto-Coupler Feedback, D0007A (SOIC-7); Alternate Manufacturer: Texas Instruments; SizeAreaWB_mm2: 55.2; U/M: EA; SizeZ_mm: 1.75; SizeX_mm: 6.0; SizeY_mm: 4.9; SizeArea_mm2: 29.4; CompType: IC; AEC Category: Q200; AEC Qualified: N
footprint D0007A_N (SOIC, 7-Leads, Body 4.9x3.9mm, Pitch 1.27mm, IPC Medium Density)
footprint D0007A_L (SOIC, 7-Leads, Body 4.9x3.9mm, Pitch 1.27mm, IPC High Density)
footprint D0007A_M (SOIC, 7-Leads, Body 4.9x3.9mm, Pitch 1.27mm, IPC Low Density)
pins: 1 VDD (power), 2 VS (in), 3 FB (in), 4 GND (power), 5 CS (in), 6 DRV (out), 8 HV (power)
1 alternate drawing of the same symbol

## CMP-0074756-2
designator U?, comment LMR33620ADDAR
3.8V to 36V 3A/2A Synchronous Step-Down Voltage Regulator, DDA0008J (SOIC-8); Manufacturer: Texas Instruments; SizeX_mm: 5.99; SizeY_mm: 4.89; CompType: IC; SizeZ_mm: 1.7; SizeArea_mm2: 29.2911; SizeAreaWB_mm2: 55.0511; U/M: EA
footprint DDA0008J (SOIC, 8-Leads, Body 4.9x3.9mm, Pitch 1.27mm, Exposed Pad)
footprint DDA0008J_NV (SOIC, 8-Leads, Body 4.9x3.9mm, Pitch 1.27mm, Exposed Pad)
pins: 1 PGND (power), 2 VIN (power), 3 EN (in), 4 PG (oc), 5 FB (in), 6 VCC (power), 7 BOOT (power), 8 SW (power), 9 AGND

## CMP-0076889-2
designator D?
Diode, P-N, 1000 V, 1 A, SMB; PartNumber: RS1MB-13-F; Manufacturer: Diodes Inc.; Manufacturer: Diodes; Vf_V: 1.3V; Value: 1000V; Value1: 1A; Vr_V: 1kV; TJmax_C: 150°C; RJC_CperW: 20.0; SizeAreaWB_mm2: 44.156; SizeArea_mm2: 21.336; SizeX_mm: 5.6; SizeY_mm: 3.81; SizeZ_mm: 2.6; AEC Category: Q101; Green_Lifecycle: Active; Green_REACh: Passed
footprint SMB (Molded Diode, 2-Leads, Body 5.4x3.6mm, IPC Medium Density, based on OnSemi component dimensions)
pins: 1 K, 2 A

## CMP-0076995-2
designator D?  value 200V  Value1: 4A
Diode, Schottky, 200 V, 4 A, SMC; PartNumber: MBRS4201T3G; Manufacturer: ON Semiconductor; Vf_V: 860mV; Value2: 0.86V; TJmax_C: 150°C; SizeAreaWB_mm2: 83.2686; SizeArea_mm2: 50.5686; SizeX_mm: 8.13; SizeY_mm: 6.22; SizeZ_mm: 2.6; AEC Category: Q101; Green_REACh: Incomplete; Green_Lifecycle: Not Set
footprint SMC (Molded Diode, 2-Leads, Body 6.9x5.8mm, IPC Medium Density, based on OnSemi component dimensions and land patterns)
pins: 1 K, 2 A

## CMP-0077027-2
designator D?
Diode, Ultrafast, 600 V, 1 A, SMA; PartNumber: US1J-13-F; Manufacturer: Diodes Inc.; Manufacturer: Diodes; Vf_V: 1.7V; Value: 600V; Value1: 1A; TJmax_C: 150°C; SizeAreaWB_mm2: 37.3428; SizeArea_mm2: 16.3228; SizeX_mm: 5.59; SizeY_mm: 2.92; SizeZ_mm: 2.87; AEC Category: Q101; Green_Lifecycle: Active; Green_REACh: Passed
footprint SMA (Molded Diode, 2-Leads, Body 4.3x2.6mm, IPC Medium Density, based on OnSemi component dimensions and land pattern)
pins: 1 K, 2 A

## CMP-0078613-2
designator RT?, comment 10D2-11LD
NTC Thermistors 10ohms 3.1amps Straight Lead; Manufacturer: Semitec; AEC Qualified: No; SizeZ_mm: 15mm; Symbol Name: SYM-10D2-11LD; AEC Category: Q101; CompType: BJT
footprint FP-10D2-11LD_RADIAL-0
pins: 1, 2

## CMP-0078615-2
designator D?, comment D3SBA60-7000
Bridge Rectifiers VRM=600 IFSM=80; Manufacturer: Shindengen; Vr_V: 600V; Symbol Name: SYM-D3SBA60-7000; TJmax_C: 150°C; CompType: Diode; AEC Qualified: No; SizeZ_mm: 19mm; AEC Category: Q101
footprint FP-D3SBA60-7000_Thin-SIP-Recommended_Land_Pattern
pins: 1 +, 2 ~, 3 ~, 4 -

## CMP-0080613-1
designator C?, comment ValueDisplayed: 2200pF  (hidden comment: VY2222M35Y5UG6TV5)
CAP, CERM, 2200 pF, X1 440 VAC/Y2 300 VAC, +/- 20%, Y5U, Body9x5mm; Manufacturer: Vishay-Bccomponents; TaMin_C: -40°C; Polarized: N; AC_Safety: X1Y2; SizeAreaWB_mm2: 77; U/M: EA; Value: 2200pF; TaMax_C: 125°C; VAC_Y: 300V; VAC_X: 440V; SizeZ_mm: 13; SizeX_mm: 9; SizeY_mm: 5; Cap_Case: 9x5mm; SizeArea_mm2: 45; CompType: Capacitor; Cap_F: 2.2nF; AEC Category: Q200
footprint VY2_900x500_5 (TH, 2-Leads, Body 9x5mm, Lead Spacing 5mm)
pins: 1, 2

## CMP-0081060-1
designator C?, comment ValueDisplayed: 3300pF  (hidden comment: C0603C332F5GACTU)
CAP, CERM, 3300 pF, 50 V,+/- 1%, C0G/NP0, 0603; Manufacturer: Kemet; Polarized: N; CompType: Capacitor; Value: 3300pF; U/M: EA; Cap_F: 3.3nF; VDC_V: 50V; TaMin_C: -55°C; TaMax_C: 125°C; Cap_Case: 0603; SizeArea_mm2: 1.28; SizeAreaWB_mm2: 4.68; SizeX_mm: 1.6; SizeY_mm: 0.8; SizeZ_mm: 1; AEC Category: Q200; Green_Lifecycle: Active; Green_REACh: Passed
footprint 0603 (0603 from SM-752 data)
footprint 0603M (0603 from SM-752 data)
footprint 0603L (0603 from SM-752 data)
footprint 0603_HV (Ernesto recommended land pattern.  26 mil between pads.)
footprint 0603S
pins: 1, 2

## CMP-0084725-1
designator U?, comment TL431LIBQDBZR
Programmable Shunt Regulator with Optimized Reference Current, DBZ0003A (SOT-23-3); Manufacturer: Texas Instruments; SizeZ_mm: 1.12; CompType: IC; SizeX_mm: 2.5; SizeY_mm: 3; SizeAreaWB_mm2: 14; AEC Category: Q200; SizeArea_mm2: 7.5; AEC Qualified: N
footprint DBZ0003A_N (SOT23, 3-Leads, Body 2.9x1.3mm, Pitch 0.95mm, Lead Span 2.4mm, IPC Medium Density)
footprint DBZ0003A_M (SOT23, 3-Leads, Body 2.9x1.3mm, Pitch 0.95mm, Lead Span 2.4mm, IPC Low Density)
footprint DBZ0003A_L (SOT23, 3-Leads, Body 2.9x1.3mm, Pitch 0.95mm, Lead Span 2.4mm, IPC High Density)
pins: 1 CATHODE, 2 REF (in), 3 ANODE

## CMP-0086019-2
designator Q?, comment TLP292(GR-TPL,E
OPTOISOLATOR 3.75KV TRANS 4-SO; Manufacturer: Toshiba; CTR (Max): 300%; CTR (Min): 100%; Symbol Name: SYM-TLP292(GR-TPL,E; SizeZ_mm: 2.3mm
footprint FP-TLP292(GR-TPL,E_SO4-IPC_A
footprint FP-TLP292(GR-TPL,E_SO4-IPC_C
footprint FP-TLP292(GR-TPL,E_SO4-Recommended_Land_Pattern
footprint FP-TLP292(GR-TPL,E_SO4-IPC_B
pins: 1 Anode/Cathode, 2 Cathode/Anode, 3 Emitter, 4 Collector

## CMP-0086362-1
designator H?, comment V6560W
Heat Sink TO-220; Manufacturer: Assman WSW; Manufacturer: Assmann
footprint HSINK_V6560W (Heat Sink TO-220)
pins: 1, 2

## CMP-0086690-2
designator L?, comment Ind_H: 5.5mH  (hidden comment: 750343092)
Power Common Mode Choke; Manufacturer: Wurth Electronics; SizeZ_mm: 18.5mm; DCR_ohm: 0.04; Symbol Name: SYM-750343092; AEC Qualified: No
footprint FP-750343092_PTH_14MM0_8MM89-0
pins: 1, 2, 3, 4

## CMP-0086795-1
designator Q?, comment TK10A80W
N-Channel 650V 9A (Tc) 22W (Tc) Through Hole PG-TO220 Full Pack; PartNumber: IPAW60R360P7SXKSA1; Manufacturer: Infineon; QgTyp_nC: 13nC @ 10V; Vgs_V: 20V; AEC Qualified: No; SizeZ_mm: 18.57mm; ChMode: False; Rdson45_ohm: 0.3; Symbol Name: SYM-IPAW60R360P7SXKSA1
footprint FP-IPAW60R360P7SXKSA1_PG-TO220-3-MFG
pins: 1 Gate, 2 Drain, 3 Source

## CMP-0090082-1
designator C?, comment ValueDisplayed: 4.7uF  (hidden comment: CGA4J1X7R1H475K125AC)
Cap Ceramic 4.7uF 50V X7R 10% Pad SMD 0805 +125°C Automotive T/R; Manufacturer: TDK Corporation; Manufacturer: TDK; Value: 4.7µF; Tolerance_%: 0.1%; TempCo: 15%; SizeZ_mm: 1.45mm; AEC Qualified: Yes; AEC Grade: Grade 1
footprint FP-CGA4J1X7R1H475K125AC_0805-MFG
footprint FP-CGA4J1X7R1H475K125AC_0805-IPC_C
footprint FP-CGA4J1X7R1H475K125AC_0805-IPC_B
footprint FP-CGA4J1X7R1H475K125AC_0805-IPC_A
pins: 1, 2

## CMP-0092204-1
designator R?, comment value 100k  (hidden comment: CRCW0402100KFKEDC)
100 kOhms ±1% 0.063W, 1/16W Chip Resistor 0402 (1005 Metric)  Thick Film; Manufacturer: Vishay; Power_W: 63mW; AEC Qualified: No; TempCo: 100ppm/°C; SizeZ_mm: 0.35mm; VDC_V: 50V
footprint FP-CRCW0402100KFKEDC_0402-MFG
footprint FP-CRCW0402100KFKEDC_0402-IPC_C
footprint FP-CRCW0402100KFKEDC_0402-IPC_B
footprint FP-CRCW0402100KFKEDC_0402-IPC_A
pins: 1, 2

## CMP-0098714-1
designator L?  Inductance: 10uH
WE-HCC SMT High Current Cube Inductor, size 1090, 10uH, 9A, 23.1mOhm; Manufacturer: Wurth Elektronik; Manufacturer Part Number: 7443331000; Manufacturer: Wurth Electronics; Material: Ferrite; Case/Size Code: 1090; DC Resistance: 22.75mOhm; Rated Inductance: 5.5uH; Saturation Current: 11.7A; Self Resonant Frequency: 35MHz
footprint WE-HCC_1090 (SMT High Current Cube Inductor, 2-Leads, body 10.9x10mm)
pins: 1, 2

## ER28-17
designator T?, comment 750345036
300uH, ER28-17,TH; Manufacturer: Wurth; SymbolCreator: Use LDAP id; SymbolVersion: use current date i.e. 2008-05-20
footprint EE28 from Customer
pins: 1, 2, 3, 4, 5, 8, 9, 11, 12

## LTV-817S
designator U?
Optocoupler, 5 kV, 50-600% CTR, SMT; Manufacturer: Lite-On; CTR (Min): 50%; CTR (Max): 600%; Voltage_Isolation_Vrms: 5000V; SizeAreaWB_mm2: 80.256; SizeArea_mm2: 46.736; SizeX_mm: 10.16; SizeY_mm: 4.6
footprint DIP254P762X350-4
pins: 1 A, 2 K, 3 E, 4 C
1 alternate drawing of the same symbol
